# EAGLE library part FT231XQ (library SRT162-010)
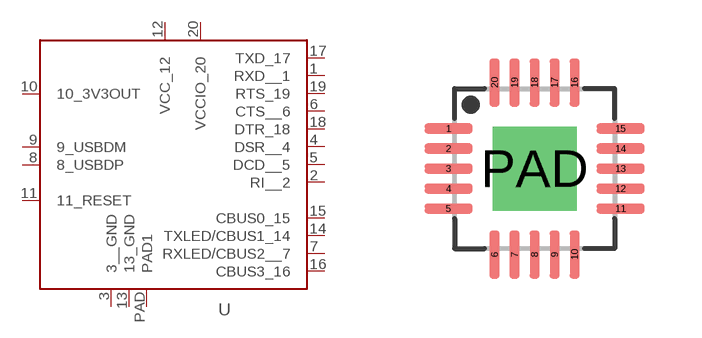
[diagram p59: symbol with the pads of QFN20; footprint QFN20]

Designator prefix U

## FT231XQ  [QFN20]
1  RXD__1  pas
2  RI__2  pas
3  3__GND  pwr
4  DSR__4  pas
5  DCD__5  pas
6  CTS__6  pas
7  RXLED/CBUS2__7  pas
8  8_USBDP  pas
9  9_USBDM  pas
10  10_3V3OUT  sup
11  11_RESET  pas
12  VCC_12  pwr
13  13_GND  pwr
14  TXLED/CBUS1_14  pas
15  CBUS0_15  pas
16  CBUS3_16  pas
17  TXD_17  pas
18  DTR_18  pas
19  RTS_19  pas
20  VCCIO_20  pwr
PAD  PAD1  pwr

## Footprint QFN20 (pad centres in mm)
smd 1.2 x 0.25: 1 -2.15,1; 2 -2.15,0.5; 3 -2.15,0; 4 -2.15,-0.5; 5 -2.15,-1; 11 2.15,-1; 12 2.15,-0.5; 13 2.15,0; 14 2.15,0.5; 15 2.15,1
smd 0.25 x 1.2: 6 -1,-2.15; 7 -0.5,-2.15; 8 0,-2.15; 9 0.5,-2.15; 10 1,-2.15; 16 1,2.15; 17 0.5,2.15; 18 0,2.15; 19 -0.5,2.15; 20 -1,2.15
drill 1.4 pad 2.1 square: PAD 0,0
